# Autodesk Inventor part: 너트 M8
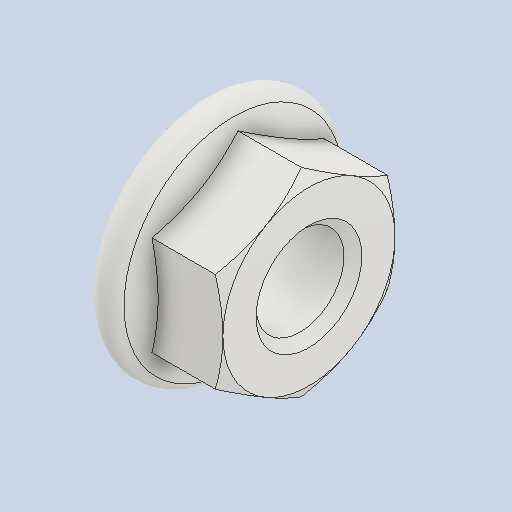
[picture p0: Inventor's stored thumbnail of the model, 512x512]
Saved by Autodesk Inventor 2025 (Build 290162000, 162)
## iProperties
Created: 2025-08
Part Number: 너트 M8
Material: 스테인리스강
Description: 플랜지붙이 6각 너트 - 일반 스레드
Document SubType Name: Modeling
Designer: infra028
Density: 8 g/cm^3
Appearance: 기본값
Author: jhkim
Sending System: Autodesk Inventor 2026
Preprocessor: ST-DEVELOPER v20.1
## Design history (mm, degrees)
feature "Solid1"
node "솔리드1"
